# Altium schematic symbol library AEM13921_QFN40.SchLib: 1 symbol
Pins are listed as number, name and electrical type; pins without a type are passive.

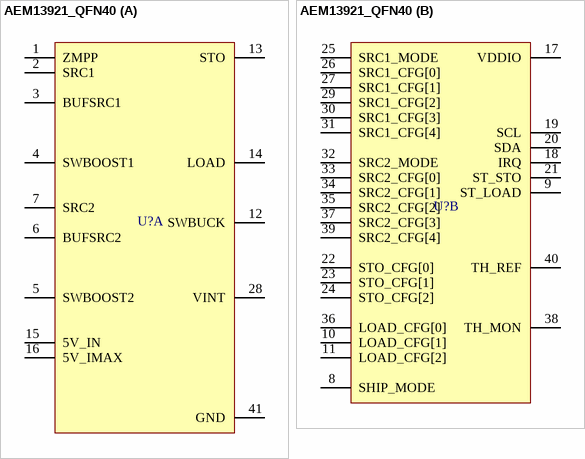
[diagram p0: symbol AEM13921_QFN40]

## AEM13921_QFN40
designator U?  (value not drawn)
AEM13921 QFN40
footprint QFN40_5x5mm_pitch0.4mm_ASE_98A0040QN185 (QFN40 body 5x5mm pitch 0.4mm Manufacturer ASE)
part A pins: 1 ZMPP, 2 SRC1, 3 BUFSRC1, 4 SWBOOST1, 5 SWBOOST2, 6 BUFSRC2, 7 SRC2, 12 SWBUCK, 13 STO, 14 LOAD, 15 5V_IN, 16 5V_IMAX, 28 VINT, 41 GND
part B pins: 8 SHIP_MODE, 9 ST_LOAD, 10 LOAD_CFG[1], 11 LOAD_CFG[2], 17 VDDIO, 18 IRQ, 19 SCL, 20 SDA, 21 ST_STO, 22 STO_CFG[0], 23 STO_CFG[1], 24 STO_CFG[2], 25 SRC1_MODE, 26 SRC1_CFG[0], 27 SRC1_CFG[1], 29 SRC1_CFG[2], 30 SRC1_CFG[3], 31 SRC1_CFG[4], 32 SRC2_MODE, 33 SRC2_CFG[0], 34 SRC2_CFG[1], 35 SRC2_CFG[2], 36 LOAD_CFG[0], 37 SRC2_CFG[3], 38 TH_MON, 39 SRC2_CFG[4], 40 TH_REF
